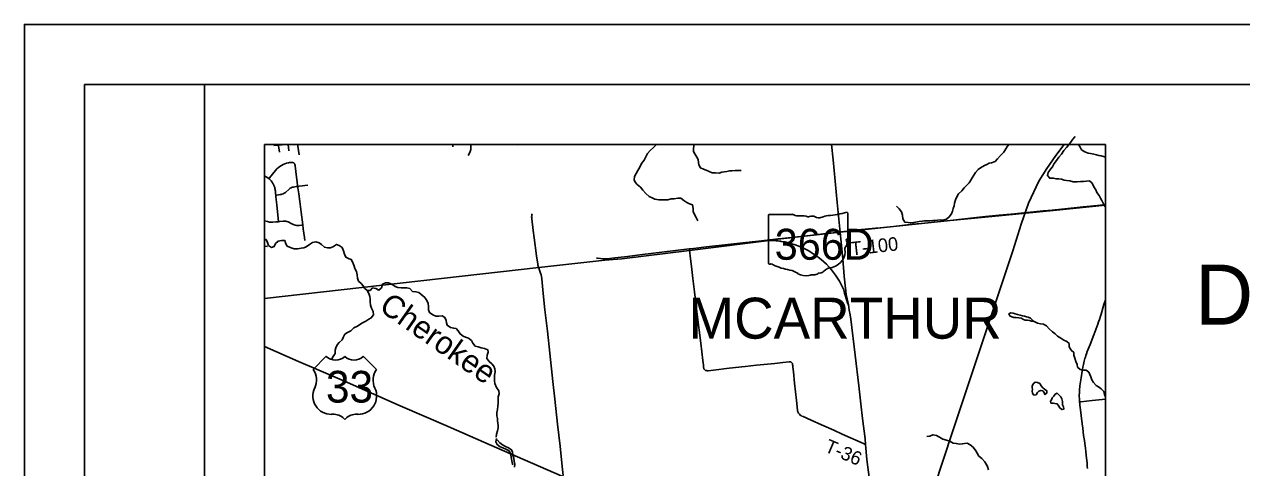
# Model space of a CAD drawing. Extents: x -5.9 to 34, y 0 to 22.
# Drawn here: x 0 to 10.13, y 18.31 to 22 of the extents above; entities that cross this region are included whole.
import ezdxf

# ---------------------------------------------------------------- set-up
doc = ezdxf.new("R2010")
doc.units = 0
for name, color, linetype in [('GM_X_County_Road', 7, 'Continuous'), ('GM_X_Minor_Lake', 7, 'Continuous'), ('GM_X_Minor_River', 7, 'Continuous'), ('GM_X_Minor_River_Text', 7, 'Continuous'), ('GM_X_Rail_Line', 7, 'Continuous'), ('GM_X_State_Location', 7, 'Continuous'), ('GM_X_State_Route', 7, 'Continuous'), ('GM_X_State_Shield', 7, 'Continuous'), ('GM_X_Township_Road', 7, 'Continuous'), ('GM_X_Township_Road_Text', 7, 'Continuous'), ('GM_X_Township_Text', 7, 'Continuous'), ('GM_X_US_Route', 7, 'Continuous'), ('GM_X_US_Shield', 7, 'Continuous'), ('SH_Border', 7, 'Continuous'), ('SH_Cut_Line', 7, 'Continuous'), ('SH_Data', 7, 'Continuous'), ('SH_Text', 7, 'Continuous')]:
    doc.layers.add(name, color=color, linetype=linetype)

msp = doc.modelspace()

# ---------------------------------------------------------------- linework, layer by layer
at = {"layer": 'GM_X_County_Road'}
for points in [[(3.567, 20.979), (3.566, 20.987), (3.565, 21)], [(8.85, 18.302), (8.849, 18.32), (8.847, 18.349), (8.845, 18.369), (8.843, 18.389), (8.84, 18.413), (8.836, 18.444), (8.833, 18.471), (8.828, 18.509), (8.825, 18.535), (8.819, 18.577), (8.815, 18.606), (8.811, 18.637), (8.806, 18.673), (8.797, 18.743), (8.789, 18.812), (8.788, 18.826), (8.786, 18.838), (8.785, 18.857), (8.784, 18.872), (8.783, 18.886), (8.782, 18.901), (8.782, 18.916), (8.783, 18.929), (8.783, 18.94), (8.784, 18.951), (8.784, 18.966), (8.786, 18.978), (8.787, 18.989), (8.797, 19.057), (8.8, 19.075), (8.803, 19.092), (8.806, 19.112), (8.809, 19.129), (8.812, 19.147), (8.817, 19.168), (8.82, 19.183), (8.823, 19.197), (8.826, 19.207), (8.829, 19.218), (8.833, 19.23), (8.837, 19.244), (8.842, 19.258), (8.848, 19.275), (8.872, 19.335), (8.903, 19.415), (8.937, 19.504), (8.943, 19.522), (8.95, 19.542), (8.959, 19.57), (8.964, 19.586), (8.979, 19.637), (8.988, 19.667), (9, 19.706)]]:
    msp.add_lwpolyline(points, dxfattribs=at)
at = {"layer": 'GM_X_Minor_Lake'}
for points in [[(8.401, 19.528), (8.376, 19.554), (8.358, 19.562), (8.342, 19.566), (8.327, 19.57), (8.309, 19.574), (8.291, 19.578), (8.268, 19.583), (8.25, 19.589), (8.233, 19.596), (8.214, 19.599), (8.197, 19.591), (8.201, 19.58)], [(8.201, 19.58), (8.204, 19.573), (8.22, 19.565), (8.239, 19.56), (8.258, 19.558), (8.279, 19.557), (8.298, 19.553), (8.317, 19.543), (8.333, 19.538), (8.35, 19.537), (8.367, 19.534), (8.384, 19.53), (8.401, 19.528)], [(8.508, 18.926), (8.512, 18.93), (8.512, 18.95), (8.494, 18.963), (8.478, 18.974), (8.466, 18.99), (8.453, 19.01), (8.435, 19.019), (8.416, 19.02), (8.399, 19.006), (8.391, 18.988), (8.391, 18.973), (8.392, 18.962)], [(8.392, 18.962), (8.391, 18.946), (8.393, 18.928), (8.405, 18.913), (8.423, 18.915), (8.434, 18.935), (8.447, 18.947), (8.463, 18.952), (8.478, 18.948), (8.49, 18.934), (8.497, 18.918), (8.508, 18.926)], [(8.55, 18.873), (8.542, 18.862), (8.547, 18.846), (8.564, 18.846), (8.579, 18.843), (8.599, 18.839), (8.613, 18.822), (8.621, 18.807), (8.638, 18.792), (8.651, 18.797)], [(8.651, 18.797), (8.655, 18.798), (8.65, 18.816), (8.644, 18.832), (8.642, 18.849), (8.643, 18.861), (8.636, 18.881), (8.629, 18.899), (8.612, 18.915), (8.598, 18.929), (8.582, 18.922), (8.57, 18.904), (8.558, 18.889), (8.55, 18.873)]]:
    msp.add_lwpolyline(points, dxfattribs=at)
at = {"layer": 'GM_X_Minor_River'}
msp.add_line((4.099, 21), (4.105, 20.993), dxfattribs=at)
for points in [[(3.717, 21), (3.717, 20.984), (3.716, 20.959), (3.708, 20.934), (3.694, 20.907)], [(5.264, 21), (5.237, 20.974), (5.209, 20.951), (5.188, 20.924), (5.173, 20.897), (5.159, 20.87), (5.137, 20.842), (5.124, 20.812), (5.108, 20.783), (5.094, 20.757), (5.079, 20.733), (5.076, 20.705), (5.086, 20.685), (5.103, 20.666), (5.13, 20.643), (5.15, 20.618), (5.173, 20.591), (5.203, 20.568), (5.227, 20.556), (5.249, 20.545), (5.283, 20.54), (5.304, 20.539), (5.332, 20.54), (5.358, 20.539), (5.385, 20.546), (5.41, 20.548), (5.441, 20.552), (5.465, 20.553), (5.491, 20.533), (5.514, 20.517), (5.537, 20.505), (5.562, 20.498), (5.568, 20.467), (5.568, 20.443), (5.579, 20.417), (5.593, 20.391), (5.607, 20.365)], [(5.573, 21), (5.573, 20.988), (5.572, 20.963), (5.571, 20.941), (5.581, 20.922), (5.599, 20.895), (5.61, 20.876), (5.613, 20.849), (5.614, 20.829), (5.629, 20.804), (5.655, 20.793), (5.677, 20.786), (5.701, 20.775), (5.727, 20.765), (5.755, 20.764), (5.785, 20.762), (5.807, 20.768), (5.826, 20.772), (5.849, 20.776), (5.87, 20.78), (5.89, 20.781), (5.918, 20.783), (5.947, 20.784), (5.969, 20.783)], [(8.196, 21), (8.185, 20.985), (8.171, 20.964)], [(8.747, 21.067), (8.729, 21.043), (8.709, 21.015), (8.692, 20.994), (8.676, 20.975), (8.655, 20.949), (8.634, 20.919), (8.612, 20.894), (8.594, 20.866), (8.573, 20.841), (8.559, 20.815), (8.544, 20.795), (8.524, 20.767), (8.518, 20.741), (8.536, 20.719), (8.567, 20.718), (8.59, 20.713), (8.613, 20.713), (8.635, 20.71), (8.656, 20.703), (8.677, 20.699), (8.705, 20.696), (8.732, 20.69), (8.764, 20.689), (8.793, 20.691), (8.818, 20.692), (8.842, 20.694), (8.867, 20.696), (8.889, 20.677), (8.905, 20.646), (8.92, 20.622), (8.93, 20.601), (8.948, 20.575), (8.96, 20.554), (8.97, 20.533), (8.983, 20.505), (8.996, 20.484), (9, 20.478)], [(8.775, 21), (8.79, 20.976), (8.802, 20.956), (8.83, 20.939), (8.857, 20.928), (8.876, 20.924), (8.905, 20.919), (8.925, 20.914), (8.946, 20.909), (8.965, 20.906), (8.993, 20.898), (9, 20.896)], [(8.171, 20.964), (8.155, 20.936), (8.128, 20.908), (8.103, 20.88), (8.082, 20.858), (8.051, 20.846), (8.032, 20.843), (8.012, 20.832), (7.993, 20.824), (7.96, 20.804), (7.94, 20.791), (7.919, 20.766), (7.905, 20.744), (7.892, 20.721), (7.879, 20.702), (7.865, 20.681), (7.845, 20.66), (7.825, 20.639), (7.804, 20.615), (7.778, 20.59), (7.764, 20.565), (7.752, 20.539), (7.745, 20.51), (7.74, 20.489), (7.732, 20.468), (7.726, 20.445), (7.718, 20.422), (7.7, 20.397), (7.678, 20.378), (7.647, 20.37), (7.624, 20.371), (7.603, 20.369), (7.581, 20.367), (7.562, 20.366), (7.542, 20.364), (7.516, 20.364), (7.494, 20.363), (7.474, 20.362), (7.449, 20.358), (7.42, 20.353), (7.401, 20.35), (7.379, 20.348), (7.358, 20.349), (7.33, 20.353), (7.313, 20.382), (7.311, 20.411), (7.302, 20.438), (7.284, 20.463), (7.261, 20.485)], [(2, 20.211), (2.012, 20.208), (2.024, 20.183), (2.032, 20.159), (2.057, 20.143), (2.081, 20.149), (2.091, 20.174), (2.113, 20.196), (2.141, 20.2), (2.168, 20.2), (2.176, 20.172), (2.189, 20.153), (2.22, 20.138), (2.247, 20.132), (2.276, 20.132), (2.304, 20.136), (2.326, 20.139), (2.346, 20.147), (2.373, 20.167), (2.398, 20.185), (2.426, 20.188), (2.454, 20.18), (2.473, 20.167), (2.498, 20.144), (2.524, 20.138), (2.549, 20.139), (2.574, 20.149), (2.599, 20.167), (2.622, 20.16), (2.645, 20.141), (2.658, 20.115), (2.665, 20.087), (2.677, 20.061), (2.703, 20.049), (2.722, 20.041), (2.735, 20.016), (2.745, 19.987), (2.751, 19.967), (2.764, 19.941), (2.771, 19.914), (2.774, 19.888), (2.782, 19.862), (2.804, 19.843), (2.822, 19.823), (2.833, 19.804), (2.855, 19.783), (2.879, 19.784), (2.899, 19.806), (2.926, 19.801), (2.952, 19.788), (2.972, 19.807)], [(2, 20.153), (2.001, 20.153), (2.025, 20.151)], [(2.855, 19.783), (2.867, 19.76), (2.876, 19.735), (2.879, 19.713), (2.879, 19.691), (2.882, 19.663), (2.891, 19.637), (2.904, 19.608), (2.907, 19.581), (2.888, 19.556), (2.868, 19.544), (2.843, 19.528), (2.815, 19.516), (2.793, 19.502), (2.773, 19.486), (2.744, 19.474), (2.718, 19.449), (2.691, 19.433), (2.669, 19.42), (2.655, 19.393), (2.645, 19.372), (2.622, 19.351), (2.605, 19.331), (2.593, 19.307), (2.588, 19.287), (2.587, 19.26), (2.57, 19.235), (2.559, 19.215)], [(2.972, 19.807), (2.982, 19.836), (3.008, 19.847), (3.031, 19.847), (3.059, 19.836), (3.086, 19.818), (3.108, 19.808), (3.136, 19.807), (3.163, 19.806), (3.183, 19.805), (3.209, 19.8), (3.232, 19.776), (3.26, 19.774), (3.283, 19.766), (3.334, 19.726), (3.352, 19.7), (3.362, 19.675), (3.364, 19.65), (3.365, 19.624), (3.374, 19.6), (3.4, 19.582), (3.425, 19.57), (3.45, 19.571), (3.478, 19.573), (3.501, 19.56), (3.511, 19.533), (3.514, 19.514), (3.521, 19.495), (3.549, 19.475), (3.575, 19.47), (3.594, 19.467), (3.611, 19.447), (3.628, 19.422), (3.652, 19.405), (3.673, 19.396), (3.697, 19.388), (3.724, 19.367), (3.733, 19.345), (3.752, 19.321), (3.778, 19.315), (3.804, 19.307), (3.832, 19.301), (3.858, 19.29), (3.86, 19.27), (3.854, 19.245), (3.851, 19.218), (3.871, 19.192), (3.891, 19.174), (3.909, 19.154), (3.917, 19.133), (3.919, 19.107), (3.914, 19.078), (3.914, 19.051), (3.915, 19.032), (3.918, 19.01), (3.931, 18.977), (3.949, 18.949), (3.952, 18.924), (3.946, 18.898), (3.945, 18.845), (3.941, 18.821), (3.938, 18.793), (3.934, 18.767), (3.934, 18.741), (3.938, 18.718), (3.94, 18.698), (3.941, 18.679), (3.944, 18.66), (3.946, 18.64), (3.94, 18.615), (3.93, 18.589), (3.928, 18.563)], [(8.401, 19.528), (8.435, 19.512), (8.46, 19.507), (8.485, 19.505), (8.509, 19.491), (8.532, 19.464), (8.559, 19.441), (8.582, 19.423), (8.601, 19.405), (8.629, 19.386), (8.653, 19.37), (8.68, 19.358), (8.699, 19.342), (8.699, 19.316), (8.715, 19.288), (8.736, 19.268), (8.736, 19.246), (8.745, 19.221), (8.755, 19.194), (8.764, 19.169), (8.768, 19.146), (8.789, 19.125), (8.817, 19.121), (8.841, 19.122), (8.863, 19.104), (8.87, 19.085), (8.878, 19.064), (8.886, 19.041), (8.9, 19.017), (8.923, 18.994), (8.942, 18.983), (8.966, 18.964), (8.986, 18.942), (8.996, 18.904), (9, 18.898)], [(3.93, 18.552), (3.925, 18.525), (3.936, 18.501), (3.96, 18.481), (3.984, 18.475), (4.008, 18.464), (4.035, 18.448), (4.047, 18.425), (4.052, 18.399), (4.056, 18.379), (4.06, 18.353), (4.068, 18.333)], [(7.512, 18.569), (7.538, 18.572), (7.564, 18.583), (7.593, 18.577), (7.62, 18.562), (7.647, 18.545), (7.677, 18.537), (7.705, 18.529), (7.732, 18.512), (7.758, 18.511), (7.786, 18.504), (7.808, 18.507), (7.827, 18.511), (7.85, 18.512), (7.875, 18.499), (7.899, 18.479), (7.921, 18.45), (7.932, 18.429), (7.947, 18.405), (7.972, 18.384), (7.995, 18.357), (8.007, 18.337), (8.018, 18.318), (8.027, 18.292)], [(3.936, 18.542), (3.958, 18.515), (3.981, 18.498), (4.007, 18.486), (4.032, 18.475), (4.056, 18.458), (4.063, 18.439), (4.068, 18.413), (4.074, 18.389), (4.079, 18.364), (4.083, 18.339), (4.08, 18.314)]]:
    msp.add_lwpolyline(points, dxfattribs=at)
at = {"layer": 'GM_X_Rail_Line'}
msp.add_lwpolyline([(8.657, 21), (8.586, 20.909), (8.513, 20.8), (8.446, 20.695), (8.36, 20.512), (8.298, 20.335), (8.23, 20.114), (7.727, 18.608), (7.27, 17.218), (7.041, 16.549)], dxfattribs=at)
at = {"layer": 'GM_X_State_Route'}
for points in [[(6.719, 21), (6.733, 20.871), (6.768, 20.518), (6.79, 20.295), (6.792, 20.271)], [(2, 19.717), (4.283, 19.975), (4.833, 20.037), (4.974, 20.049), (5.538, 20.116), (6.244, 20.207), (6.249, 20.208), (6.791, 20.27), (7.681, 20.363), (8.14, 20.409), (8.593, 20.453), (9, 20.494)], [(9, 20.494), (8.593, 20.453), (8.14, 20.409), (7.681, 20.363), (6.791, 20.27), (6.249, 20.208), (6.244, 20.207), (5.538, 20.116), (4.974, 20.049), (4.833, 20.037), (4.283, 19.975), (2, 19.717)], [(6.792, 20.271), (6.76, 20.267), (6.675, 20.258), (6.539, 20.243), (6.309, 20.218), (6.275, 20.214), (6.183, 20.203)], [(6.792, 20.271), (6.813, 20.046), (6.826, 19.903), (6.836, 19.802), (6.838, 19.788), (6.84, 19.77), (6.842, 19.756), (6.843, 19.752)], [(4.764, 20.054), (4.771, 20.053), (4.796, 20.05), (4.82, 20.049), (4.843, 20.049), (4.875, 20.051), (4.916, 20.055), (5.022, 20.068), (5.124, 20.081), (5.42, 20.118), (5.536, 20.131), (5.572, 20.135), (5.68, 20.148), (5.882, 20.17), (5.982, 20.181), (6.112, 20.195), (6.183, 20.203)], [(6.183, 20.203), (6.192, 20.202), (6.2, 20.201), (6.208, 20.2), (6.222, 20.2), (6.237, 20.199), (6.258, 20.198), (6.275, 20.197), (6.286, 20.195), (6.294, 20.194)], [(6.294, 20.194), (6.3, 20.193), (6.331, 20.188), (6.361, 20.181), (6.39, 20.173), (6.418, 20.164), (6.448, 20.153), (6.472, 20.143), (6.499, 20.131), (6.53, 20.113), (6.559, 20.096), (6.585, 20.079), (6.61, 20.061), (6.633, 20.042), (6.657, 20.022), (6.677, 20.002), (6.7, 19.979), (6.72, 19.955), (6.737, 19.934), (6.752, 19.913), (6.769, 19.888), (6.785, 19.862), (6.8, 19.835), (6.811, 19.813), (6.821, 19.789), (6.829, 19.762), (6.834, 19.745), (6.855, 19.673), (6.856, 19.67), (6.858, 19.668), (6.86, 19.666)], [(6.843, 19.752), (6.845, 19.74), (6.86, 19.666)], [(6.86, 19.666), (6.868, 19.62), (6.875, 19.582), (6.88, 19.544), (6.916, 19.245), (6.947, 18.99), (6.964, 18.84), (6.979, 18.717), (6.999, 18.549), (7.003, 18.503), (7.015, 18.376), (7.036, 18.208), (7.064, 17.974), (7.084, 17.816), (7.091, 17.749)]]:
    msp.add_lwpolyline(points, dxfattribs=at)
at = {"layer": 'GM_X_State_Shield'}
for p, q in [((6.196, 20.412), (6.196, 20.011)), ((6.395, 20.418), (6.202, 20.418)), ((6.855, 20.219), (6.855, 20.428)), ((6.855, 20.219), (6.855, 20.219))]:
    msp.add_line(p, q, dxfattribs=at)
for centre, major_axis, start_param, end_param in [((6.203, 20.412), (0.00764, 0), 1.712693, 3.28349), ((6.441, 20.465), (0.0741, 0), 4.042523, 4.731795), ((6.466, 20.194), (0.266, 0), 1.404758, 1.657858), ((6.526, 20.415), (0.0214, 0), 3.836095, 5.185415), ((6.557, 20.368), (0.0444, 0), 0.950623, 2.079405), ((6.615, 20.432), (0.0534, 0), 4.081561, 5.145723), ((6.709, 20.296), (0.141, 0), 1.699011, 2.107814), ((6.62, 20.964), (0.699, 0), 4.814394, 5.042369), ((6.847, 20.429), (0.00734, 0), 6.141152, 7.989035), ((6.853, 20.204), (0.0114, 0), 1.883978, 3.671073), ((6.781, 20.177), (0.0682, 0), 5.934695, 6.695948), ((6.847, 20.218), (0.00785, 0), 5.05454, 6.418171), ((6.659, 20.105), (0.175, 0), 5.101752, 6.440018), ((6.881, 20.131), (0.0496, 0), 2.387724, 3.262537), ((6.203, 20.01), (0.0077, 0), 3.00124, 4.508301), ((6.204, 20.051), (0.0588, 0), 4.665946, 4.897461), ((6.216, 19.988), (0.0212, 0), 0.519207, 1.627899), ((6.484, 20.348), (0.505, 0), 4.195997, 4.488961), ((6.733, 19.899), (0.0958, 0), 1.647645, 2.488434), ((6.334, 19.832), (0.158, 0), 0.823519, 1.323587), ((6.504, 19.986), (0.1, 0), 4.026481, 4.996735), ((6.562, 19.848), (0.0824, 0), 1.495662, 1.94098), ((6.57, 19.956), (0.0534, 0), 4.691044, 5.507374), ((6.618, 19.918), (0.015, 0), 1.147584, 2.315152), ((6.611, 19.973), (0.0565, 0), 4.937069, 5.64225)]:
    msp.add_ellipse(centre, major_axis=major_axis, ratio=0.8, start_param=start_param, end_param=end_param, dxfattribs=at)
at = {"layer": 'GM_X_Township_Road'}
for points in [[(2.077, 20.99), (2.116, 20.994), (2.146, 20.998), (2.167, 21)], [(2.123, 20.936), (2.117, 20.989), (2.116, 20.994)], [(2.203, 20.947), (2.199, 20.975), (2.196, 21)], [(2.288, 20.914), (2.278, 20.987), (2.276, 21)], [(2.037, 20.714), (2.042, 20.722), (2.067, 20.753), (2.091, 20.782), (2.103, 20.796), (2.115, 20.807), (2.128, 20.817), (2.14, 20.826), (2.154, 20.833), (2.168, 20.839), (2.182, 20.844), (2.198, 20.847), (2.208, 20.849), (2.217, 20.85), (2.222, 20.851), (2.227, 20.851), (2.229, 20.851), (2.232, 20.851), (2.236, 20.85), (2.239, 20.849), (2.241, 20.848), (2.244, 20.846)], [(2.335, 20.201), (2.332, 20.224), (2.327, 20.262), (2.322, 20.297), (2.318, 20.33), (2.304, 20.436), (2.293, 20.524), (2.284, 20.59), (2.278, 20.639), (2.276, 20.651), (2.275, 20.658), (2.271, 20.69), (2.266, 20.728), (2.254, 20.821), (2.254, 20.825), (2.252, 20.832), (2.251, 20.836), (2.25, 20.839), (2.249, 20.842), (2.247, 20.844), (2.244, 20.846)], [(2, 20.735), (2.001, 20.735), (2.013, 20.729), (2.026, 20.722), (2.037, 20.714), (2.042, 20.71), (2.047, 20.705), (2.054, 20.697), (2.063, 20.685), (2.072, 20.67), (2.076, 20.663), (2.078, 20.659), (2.081, 20.653), (2.083, 20.646), (2.085, 20.641), (2.086, 20.634), (2.088, 20.626), (2.089, 20.619), (2.09, 20.612), (2.092, 20.589), (2.094, 20.578), (2.095, 20.563), (2.102, 20.497), (2.117, 20.357)], [(2.094, 20.578), (2.102, 20.579), (2.117, 20.58), (2.129, 20.582), (2.138, 20.583), (2.145, 20.585), (2.154, 20.589), (2.162, 20.594), (2.169, 20.598), (2.173, 20.6), (2.206, 20.629), (2.214, 20.635), (2.222, 20.639), (2.231, 20.643), (2.242, 20.645), (2.264, 20.649), (2.276, 20.651), (2.289, 20.652), (2.36, 20.661)], [(6.792, 20.271), (6.802, 20.272), (6.941, 20.288), (7.085, 20.302), (7.124, 20.306), (7.237, 20.318), (7.305, 20.325), (7.394, 20.335), (7.467, 20.342), (7.629, 20.359), (7.708, 20.367), (7.901, 20.388), (8.002, 20.399), (8.115, 20.41), (8.243, 20.423), (8.322, 20.431), (8.403, 20.439), (8.483, 20.447), (8.557, 20.454), (8.688, 20.468), (8.765, 20.475), (8.816, 20.48), (8.933, 20.492), (9, 20.499)], [(4.277, 19.988), (4.276, 19.994), (4.274, 20.002), (4.265, 20.073), (4.244, 20.223), (4.237, 20.283), (4.224, 20.38), (4.224, 20.389), (4.223, 20.398), (4.224, 20.405), (4.226, 20.415), (4.228, 20.422)], [(2, 20.365), (2.023, 20.358), (2.032, 20.356), (2.042, 20.354), (2.048, 20.353), (2.053, 20.353), (2.06, 20.353), (2.068, 20.353), (2.094, 20.355), (2.109, 20.357), (2.117, 20.357), (2.128, 20.359), (2.154, 20.361), (2.168, 20.362), (2.177, 20.361), (2.186, 20.359), (2.195, 20.355), (2.227, 20.34), (2.245, 20.331), (2.255, 20.328), (2.266, 20.326), (2.277, 20.325), (2.289, 20.326), (2.306, 20.328), (2.318, 20.33)], [(7.003, 18.503), (6.997, 18.505), (6.987, 18.509), (6.972, 18.516), (6.942, 18.529), (6.878, 18.558), (6.808, 18.589), (6.738, 18.62), (6.636, 18.666), (6.55, 18.705), (6.483, 18.734), (6.474, 18.738), (6.467, 18.742), (6.463, 18.744), (6.458, 18.747), (6.452, 18.753), (6.447, 18.759), (6.444, 18.763), (6.442, 18.767), (6.44, 18.772), (6.439, 18.777), (6.437, 18.783), (6.436, 18.789), (6.428, 18.868), (6.412, 19.013), (6.403, 19.107), (6.399, 19.146), (6.398, 19.155), (6.397, 19.16), (6.396, 19.165), (6.395, 19.17), (6.394, 19.175), (6.392, 19.179), (6.389, 19.182), (6.387, 19.185), (6.384, 19.187), (6.38, 19.189), (6.376, 19.19), (6.372, 19.191), (6.366, 19.19), (6.315, 19.185), (6.248, 19.177), (6.096, 19.161), (6.002, 19.151), (5.867, 19.136), (5.737, 19.122), (5.692, 19.116), (5.687, 19.116), (5.684, 19.116), (5.68, 19.117), (5.676, 19.117), (5.672, 19.119), (5.668, 19.121), (5.665, 19.123), (5.662, 19.126), (5.66, 19.13), (5.658, 19.133), (5.657, 19.136), (5.656, 19.139), (5.655, 19.144), (5.654, 19.149), (5.653, 19.162), (5.648, 19.2), (5.631, 19.346), (5.602, 19.583), (5.58, 19.773), (5.566, 19.885), (5.554, 19.984), (5.544, 20.07), (5.537, 20.126), (5.536, 20.131)], [(4.285, 19.966), (4.279, 19.98), (4.277, 19.986), (4.277, 19.988)], [(4.487, 18.243), (4.478, 18.32), (4.46, 18.488), (4.439, 18.672), (4.417, 18.878), (4.401, 19.026), (4.374, 19.263), (4.354, 19.445), (4.334, 19.624), (4.32, 19.758), (4.307, 19.882), (4.304, 19.901), (4.302, 19.915), (4.298, 19.927), (4.295, 19.938), (4.292, 19.946), (4.287, 19.961), (4.285, 19.966)], [(8.785, 18.857), (8.796, 18.858), (8.889, 18.868), (9, 18.879)]]:
    msp.add_lwpolyline(points, dxfattribs=at)
at = {"layer": 'GM_X_US_Route'}
msp.add_lwpolyline([(2, 19.317), (2.282, 19.194), (2.432, 19.128), (2.664, 19.028), (3.129, 18.825), (3.529, 18.651), (3.826, 18.521), (4.215, 18.351), (4.488, 18.232), (4.73, 18.127), (4.813, 18.088), (4.894, 18.05), (4.952, 18.021), (5.009, 17.991), (5.074, 17.956), (5.127, 17.926), (5.229, 17.867), (5.294, 17.827), (5.356, 17.788), (5.417, 17.746), (5.483, 17.701), (5.563, 17.645), (5.642, 17.584)], dxfattribs=at)
at = {"layer": 'GM_X_US_Shield'}
for p, q in [((2.514, 19.236), (2.404, 19.126)), ((2.931, 19.126), (2.822, 19.236)), ((2.558, 18.753), (2.58, 18.753)), ((2.756, 18.753), (2.778, 18.753))]:
    msp.add_line(p, q, dxfattribs=at)
for centre, radius, start, end in [((2.591, 19.314), 0.11, 225.573, 314.427), ((2.745, 19.314), 0.11, 225.573, 314.427), ((2.278, 19.038), 0.154, 334.5471, 35.0009), ((3.057, 19.038), 0.154, 144.9991, 205.4529), ((2.556, 18.906), 0.154, 154.8319, 270.6383), ((2.779, 18.906), 0.154, 269.3617, 25.1681), ((2.58, 18.643), 0.11, 36.8699, 90), ((2.756, 18.643), 0.11, 90, 143.1301)]:
    msp.add_arc(centre, radius, start, end, dxfattribs=at)
at = {"layer": 'SH_Border'}
for points in [[(0.5, 21.5), (1.5, 21.5), (1.5, 0.5), (0.5, 0.5)], [(1.5, 21.5), (33.5, 21.5), (33.5, 0.5), (1.5, 0.5)]]:
    msp.add_lwpolyline(points, close=True, dxfattribs=at)
at = {"layer": 'SH_Cut_Line'}
msp.add_lwpolyline([(0, 0), (34, 0), (34, 22), (0, 22)], close=True, dxfattribs=at)
at = {"layer": 'SH_Data'}
for p, q in [((2, 21), (9, 21)), ((2, 21), (2, 14)), ((9, 21), (9, 14))]:
    msp.add_line(p, q, dxfattribs=at)

# ---------------------------------------------------------------- texts
at = {"layer": 'GM_X_Minor_River_Text'}
msp.add_text('Cherokee', height=0.1894, rotation=325.0277, dxfattribs=at).set_placement((2.943, 19.624))
at = {"layer": 'GM_X_State_Location'}
msp.add_text('366D', height=0.000379, rotation=0, dxfattribs=at).set_placement((6.357, 20.168))
for s in ['s', 'r']:
    msp.add_text(s, height=0.000379, dxfattribs=at).set_placement((6.518, 20.185))
at = {"layer": 'GM_X_State_Shield'}
msp.add_text('366D', height=0.2576, dxfattribs=at).set_placement((6.247, 20.04))
at = {"layer": 'GM_X_Township_Road_Text'}
for s, rotation, p in [('T-100', 6.4955, (6.886, 20.074)), ('T-36', 336.7538, (6.654, 18.446))]:
    msp.add_text(s, height=0.1136, rotation=rotation, dxfattribs=at).set_placement(p)
at = {"layer": 'GM_X_Township_Text'}
msp.add_text('MCARTHUR', height=0.3409, rotation=0, dxfattribs=at).set_placement((5.529, 19.383))
at = {"layer": 'GM_X_US_Shield'}
msp.add_text('33', height=0.2637, dxfattribs=at).set_placement((2.511, 18.851))
at = {"layer": 'SH_Text'}
msp.add_text('DEPARTMENT OF TRANSPORTATION', height=0.5, dxfattribs=at).set_placement((9.747, 19.5))

doc.saveas('drawing.dxf')
